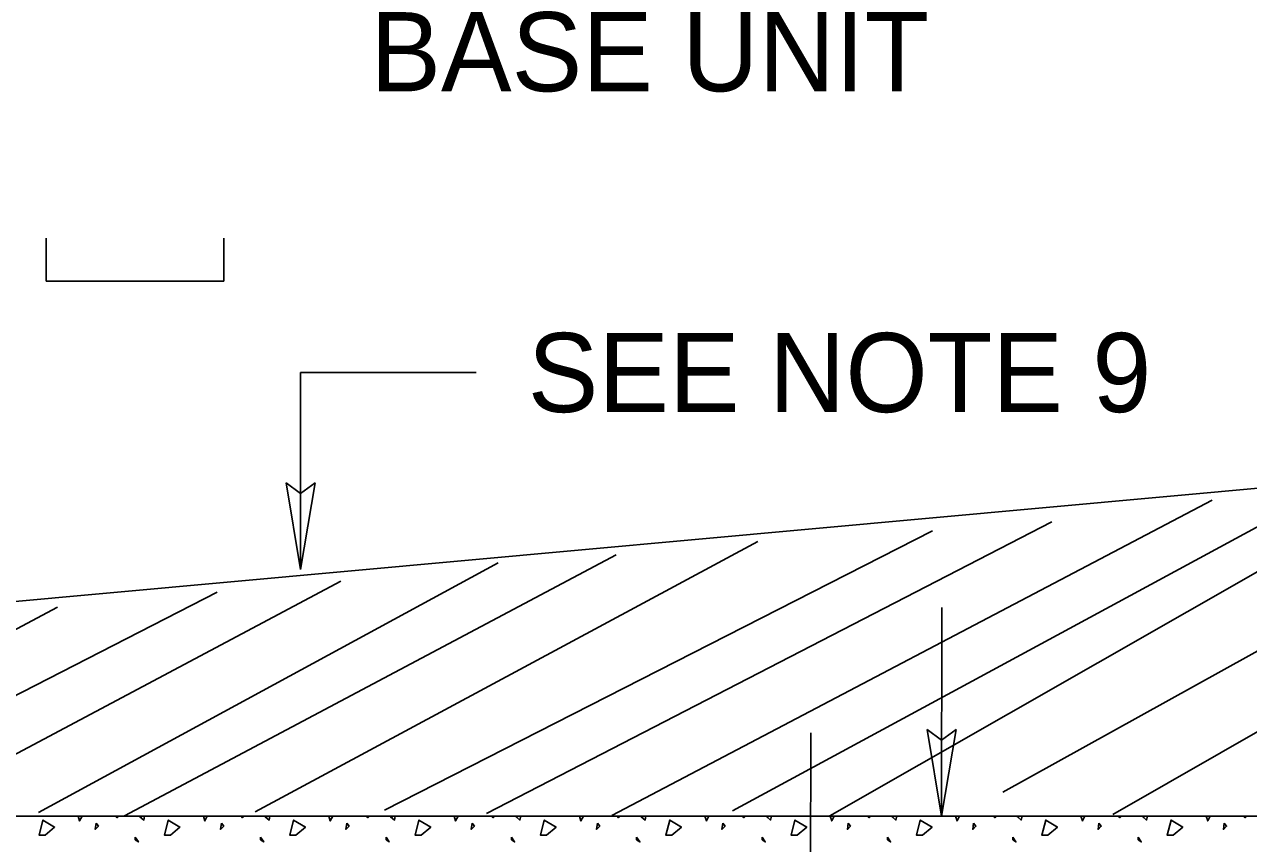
# Model space of a CAD drawing. Extents: x 9.6 to 16.8, y 2.2 to 12.2.
# Drawn here: x 11.758 to 12.686, y 7.016 to 7.637 of the extents above; entities that cross this region are included whole.
import ezdxf

# ---------------------------------------------------------------- set-up
doc = ezdxf.new("R2010")
doc.units = 0
for name, color, linetype in [('DETL-DIMS', 7, 'Continuous'), ('DETL-LINE', 7, 'Continuous'), ('DETL-NOTE', 7, 'Continuous'), ('DETL-PATT', 7, 'Continuous')]:
    doc.layers.add(name, color=color, linetype=linetype)

msp = doc.modelspace()

# ---------------------------------------------------------------- linework, layer by layer
at = {"layer": 'DETL-DIMS'}
for p, q in [((12.10024, 7.37357), (11.96729, 7.37357)), ((11.96729, 7.37357), (11.96729, 7.22416)), ((11.95631, 7.29004), (11.96729, 7.22416)), ((11.95631, 7.29004), (11.96729, 7.2818)), ((11.97827, 7.29004), (11.96729, 7.22416)), ((11.97827, 7.29004), (11.96729, 7.2818)), ((12.45296, 7.0371), (12.45327, 7.19529)), ((12.35376, 6.94224), (12.35408, 7.10043)), ((12.4421, 7.10302), (12.45296, 7.0371)), ((12.4421, 7.10302), (12.45308, 7.09475)), ((12.46406, 7.10294), (12.45296, 7.0371)), ((12.46406, 7.10294), (12.45308, 7.09475))]:
    msp.add_line(p, q, dxfattribs=at)
at = {"layer": 'DETL-LINE'}
for p, q in [((11.77451, 7.47557), (11.77451, 7.4429)), ((11.90906, 7.4429), (11.90906, 7.47557)), ((11.77451, 7.4429), (11.90906, 7.4429)), ((11.30671, 7.15941), (13.24388, 7.33624)), ((11.30592, 7.0371), (13.24639, 7.0371))]:
    msp.add_line(p, q, dxfattribs=at)
at = {"layer": 'DETL-PATT'}
for p, q in [((13.05627, 7.3098), (12.58302, 7.03835)), ((12.81808, 7.29427), (12.36831, 7.03733)), ((12.49961, 7.05545), (12.93718, 7.29827)), ((12.29471, 7.04125), (12.74584, 7.28545)), ((12.20329, 7.03769), (12.65816, 7.27671)), ((12.53671, 7.26047), (12.10812, 7.03925)), ((12.03075, 7.04176), (12.4462, 7.25361)), ((12.31396, 7.24537), (11.93278, 7.04055)), ((12.11702, 7.22929), (11.76867, 7.03992)), ((11.83384, 7.03745), (12.20655, 7.23525)), ((11.66553, 7.03875), (11.99788, 7.21541)), ((11.90412, 7.20714), (11.5849, 7.04361)), ((11.49722, 7.04424), (11.7831, 7.19561))]:
    msp.add_line(p, q, dxfattribs=at)
for points in [[(11.77365, 7.0229), (11.78082, 7.02894), (11.77196, 7.0342), (11.76898, 7.0229)], [(11.86867, 7.0229), (11.87584, 7.02894), (11.86694, 7.0342), (11.864, 7.0229)], [(11.96365, 7.0229), (11.97086, 7.02894), (11.96196, 7.0342), (11.95902, 7.0229)], [(12.05867, 7.0229), (12.06588, 7.02894), (12.05698, 7.0342), (12.054, 7.0229)], [(12.15369, 7.0229), (12.1609, 7.02894), (12.152, 7.0342), (12.14902, 7.0229)], [(12.24871, 7.0229), (12.25588, 7.02894), (12.24702, 7.0342), (12.24404, 7.0229)], [(12.34373, 7.0229), (12.3509, 7.02894), (12.342, 7.0342), (12.33906, 7.0229)], [(12.43871, 7.0229), (12.44592, 7.02894), (12.43702, 7.0342), (12.43408, 7.0229)], [(12.53373, 7.0229), (12.54094, 7.02894), (12.53204, 7.0342), (12.52906, 7.0229)], [(12.62875, 7.0229), (12.63596, 7.02894), (12.62706, 7.0342), (12.62408, 7.0229)], [(11.81231, 7.03192), (11.81161, 7.02714), (11.814, 7.02953)], [(11.90733, 7.03192), (11.90663, 7.02714), (11.90902, 7.02953)], [(12.00235, 7.03192), (12.00165, 7.02714), (12.00404, 7.02953)], [(12.09737, 7.03192), (12.09667, 7.02714), (12.09906, 7.02953)], [(12.19235, 7.03192), (12.19165, 7.02714), (12.19408, 7.02953)], [(12.28737, 7.03192), (12.28667, 7.02714), (12.28906, 7.02953)], [(12.38239, 7.03192), (12.38169, 7.02714), (12.38408, 7.02953)], [(12.47741, 7.03192), (12.47671, 7.02714), (12.4791, 7.02953)], [(12.57243, 7.03192), (12.57173, 7.02714), (12.57412, 7.02953)], [(12.66741, 7.03192), (12.66671, 7.02714), (12.66914, 7.02953)], [(11.84196, 7.02118), (11.84196, 7.01937), (11.84435, 7.01765)], [(11.93698, 7.02118), (11.93698, 7.01937), (11.93937, 7.01765)], [(12.032, 7.02118), (12.032, 7.01937), (12.03439, 7.01765)], [(12.12702, 7.02118), (12.12702, 7.01937), (12.12941, 7.01765)], [(12.222, 7.02118), (12.222, 7.01937), (12.22443, 7.01765)], [(12.31702, 7.02118), (12.31702, 7.01937), (12.31941, 7.01765)], [(12.41204, 7.02118), (12.41204, 7.01937), (12.41443, 7.01765)], [(12.50706, 7.02118), (12.50706, 7.01937), (12.50945, 7.01765)], [(12.60208, 7.02118), (12.60208, 7.01937), (12.60447, 7.01765)]]:
    msp.add_lwpolyline(points, close=True, dxfattribs=at)
for points in [[(11.79863, 7.0371), (11.79976, 7.03361), (11.80157, 7.0371)], [(11.82937, 7.0371), (11.82827, 7.036), (11.82718, 7.0371)], [(11.84878, 7.0371), (11.84549, 7.03659), (11.84847, 7.0342), (11.84902, 7.0371)], [(11.89365, 7.0371), (11.89478, 7.03361), (11.89655, 7.0371)], [(11.92439, 7.0371), (11.92329, 7.036), (11.9222, 7.0371)], [(11.9438, 7.0371), (11.94051, 7.03659), (11.94349, 7.0342), (11.94404, 7.0371)], [(11.98867, 7.0371), (11.98976, 7.03361), (11.99157, 7.0371)], [(12.01941, 7.0371), (12.01831, 7.036), (12.01722, 7.0371)], [(12.03882, 7.0371), (12.03553, 7.03659), (12.03847, 7.0342), (12.03906, 7.0371)], [(12.08365, 7.0371), (12.08478, 7.03361), (12.08659, 7.0371)], [(12.11439, 7.0371), (12.11329, 7.036), (12.1122, 7.0371)], [(12.13384, 7.0371), (12.13055, 7.03659), (12.13349, 7.0342), (12.13408, 7.0371)], [(12.17867, 7.0371), (12.1798, 7.03361), (12.18161, 7.0371)], [(12.20941, 7.0371), (12.20831, 7.036), (12.20722, 7.0371)], [(12.22882, 7.0371), (12.22553, 7.03659), (12.22851, 7.0342), (12.22906, 7.0371)], [(12.27369, 7.0371), (12.27482, 7.03361), (12.27663, 7.0371)], [(12.30443, 7.0371), (12.30333, 7.036), (12.30224, 7.0371)], [(12.32384, 7.0371), (12.32055, 7.03659), (12.32353, 7.0342), (12.32408, 7.0371)], [(12.36871, 7.0371), (12.36984, 7.03361), (12.37161, 7.0371)], [(12.39945, 7.0371), (12.39835, 7.036), (12.39725, 7.0371)], [(12.41886, 7.0371), (12.41557, 7.03659), (12.41855, 7.0342), (12.4191, 7.0371)], [(12.46373, 7.0371), (12.46482, 7.03361), (12.46663, 7.0371)], [(12.49447, 7.0371), (12.49337, 7.036), (12.49227, 7.0371)], [(12.51388, 7.0371), (12.51059, 7.03659), (12.51353, 7.0342), (12.51412, 7.0371)], [(12.55871, 7.0371), (12.55984, 7.03361), (12.56165, 7.0371)], [(12.58945, 7.0371), (12.58835, 7.036), (12.58725, 7.0371)], [(12.6089, 7.0371), (12.60561, 7.03659), (12.60855, 7.0342), (12.60914, 7.0371)], [(12.65373, 7.0371), (12.65486, 7.03361), (12.65667, 7.0371)], [(12.68447, 7.0371), (12.68337, 7.036), (12.68227, 7.0371)]]:
    msp.add_lwpolyline(points, dxfattribs=at)

# ---------------------------------------------------------------- texts
at = {"layer": 'DETL-NOTE'}
for s, p in [('BASE UNIT', (12.02016, 7.58682)), ('SEE NOTE 9', (12.13945, 7.34357))]:
    msp.add_text(s, height=0.06, dxfattribs=at).set_placement(p)

doc.saveas('drawing.dxf')
